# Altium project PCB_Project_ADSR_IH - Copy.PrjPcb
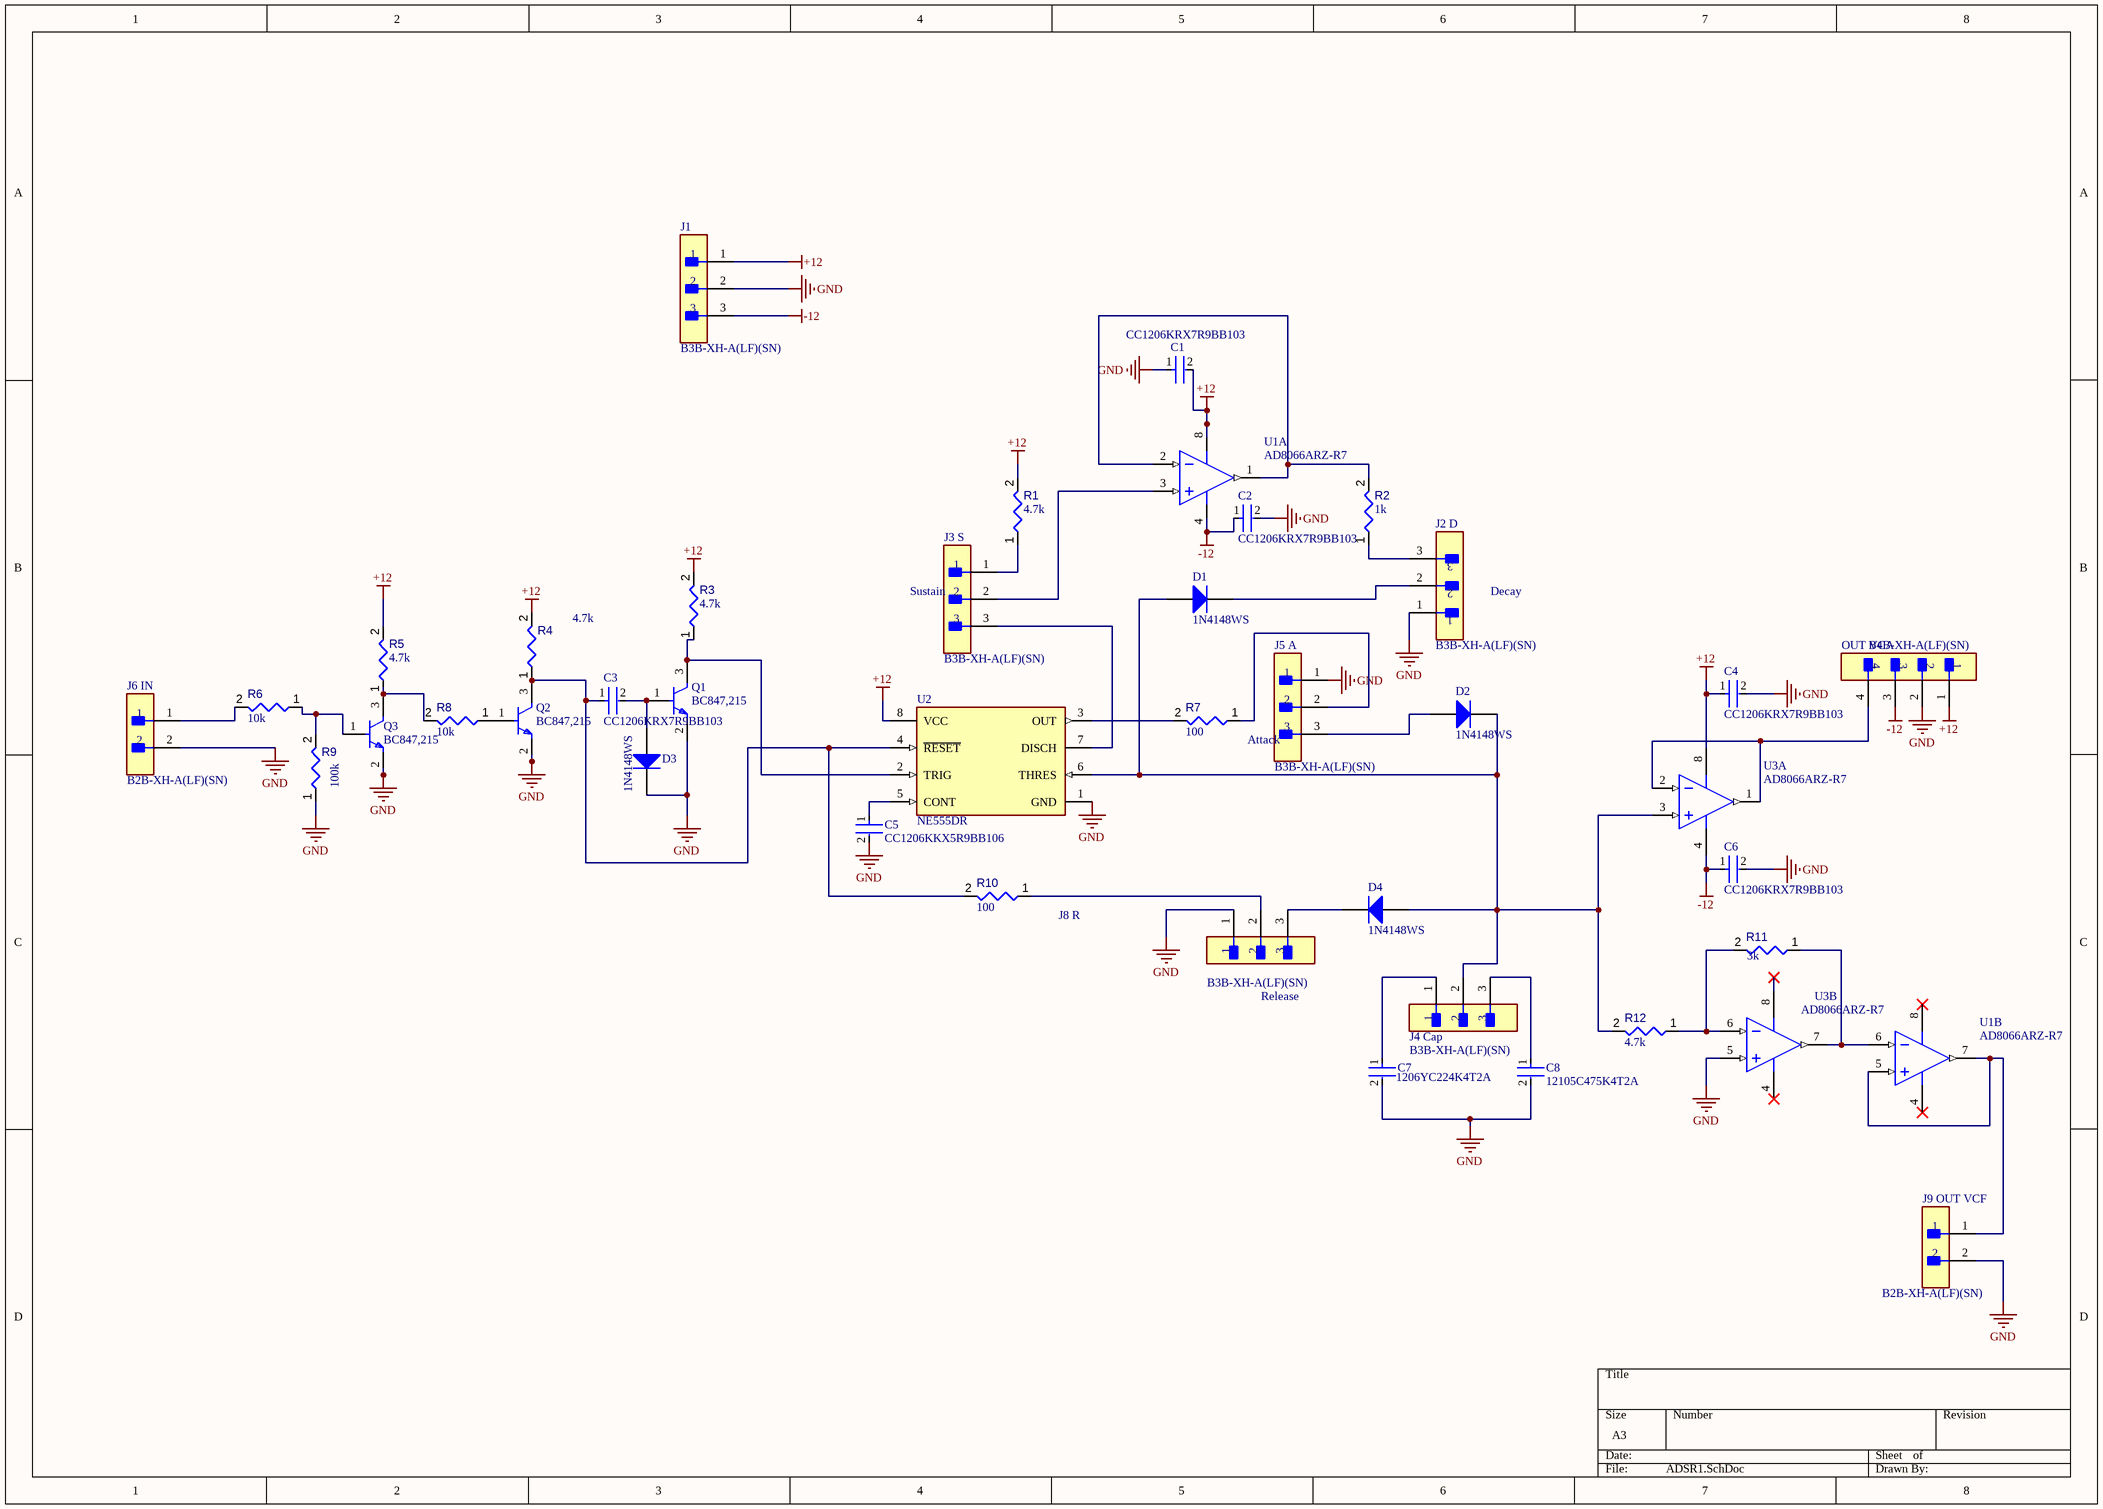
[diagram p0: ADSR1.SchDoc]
1 sheet, 39 parts. Net scope: global (net labels, ports and power ports of the same name join across sheets).
Board file: ADSR_pcb1.1.PcbDoc

## Sheet ADSR1.SchDoc: ADSR schematic
size A3; CheckedBy: Ingmar Kosmijer; Author: Hidde Huysman; CompanyName: Proj Synth; DrawnBy: Ingmar Kosmijer & Hidde Huysman; Organization: Windesheim College; Revision: 1.0; SheetNumber: 1; SheetTotal: 1

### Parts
C1  CC1206KRX7R9BB103  [FP-CC1206-1_25-MFG]
C2  CC1206KRX7R9BB103  [FP-CC1206-1_25-MFG]
C3  CC1206KRX7R9BB103  [FP-CC1206-1_25-MFG]
C4  CC1206KRX7R9BB103  [FP-CC1206-1_25-MFG]
C5  CC1206KKX5R9BB106  [FP-CC1206-FD-MFG]
C6  CC1206KRX7R9BB103  [FP-CC1206-1_25-MFG]
C7  1206YC224K4T2A  [FP-1206-L_3_2_0_2-W_1_6_0-IPC_B]
C8  12105C475K4T2A  [FP-1210-L_3_3_0_4-W_2_5_0-MFG]
D1  1N4148WS  [DIOD-SOD323-2-A_V]
D2  1N4148WS  [DIOD-SOD323-2-A_V]
D3  1N4148WS  [DIOD-SOD323-2-A_V]
D4  1N4148WS  [DIOD-SOD323-2-A_V]
J1  B3B-XH-A(LF)(SN)  [FP-B3B-XH-A_LF_SN-MFG]
J2_D  B3B-XH-A(LF)(SN)  [FP-B3B-XH-A_LF_SN-MFG]
J3_S  B3B-XH-A(LF)(SN)  [FP-B3B-XH-A_LF_SN-MFG]
J4_Cap  B3B-XH-A(LF)(SN)  [FP-B3B-XH-A_LF_SN-MFG]
J5_A  B3B-XH-A(LF)(SN)  [FP-B3B-XH-A_LF_SN-MFG]
J6_IN  B2B-XH-A(LF)(SN)  [FP-B2B-XH-A_LF_SN-MFG]
J8_R  B3B-XH-A(LF)(SN)  [FP-B3B-XH-A_LF_SN-MFG]
J9_OUT_VCF  B2B-XH-A(LF)(SN)  [FP-B2B-XH-A_LF_SN-MFG]
OUT_VCA  B4B-XH-A(LF)(SN)  [FP-B4B-XH-A_LF_SN-MFG]
Q1  BC847,215  [FP-SOT23-MFG]
Q2  BC847,215  [FP-SOT23-MFG]
Q3  BC847,215  [FP-SOT23-MFG]
R1  value 4.7k  [RESC3216X60X45ML15T20]  (hidden comment: Resistor 100k +/-1% 1206 250 mW)
R2  value 1k  [RESC2010(5025)_L]  (hidden comment: CRCW2010100RFKEF)
R3  value 4.7k  [RESC3216X60X45ML15T20]  (hidden comment: Resistor 100k +/-1% 1206 250 mW)
R4  value 4.7k  [RESC3216X60X45ML15T20]  (hidden comment: Resistor 100k +/-1% 1206 250 mW)
R5  value 4.7k  [RESC3216X60X45ML15T20]  (hidden comment: Resistor 100k +/-1% 1206 250 mW)
R6  value 10k  [RESC3216X60X45ML15T20]  (hidden comment: Resistor 100k +/-1% 1206 250 mW)
R7  value 100  [RESC3216X60X45ML15T20]  (hidden comment: Resistor 100k +/-1% 1206 250 mW)
R8  value 10k  [RESC3216X60X45ML15T20]  (hidden comment: Resistor 100k +/-1% 1206 250 mW)
R9  value 100k  [RESC3216X60X45ML15T20]  (hidden comment: Resistor 100k +/-1% 1206 250 mW)
R10  value 100  [RESC3216X60X45ML15T20]  (hidden comment: Resistor 100k +/-1% 1206 250 mW)
R11  value 3k  [RESC3216X60X45ML15T20]  (hidden comment: Resistor 100k +/-1% 1206 250 mW)
R12  value 4.7k  [RESC3216X60X45ML15T20]  (hidden comment: Resistor 100k +/-1% 1206 250 mW)
U1  AD8066ARZ-R7  [ADI-R-8_M]  (parts A,B of 2)
U2  NE555DR  [FP-D0008A-IPC_A]
U3  AD8066ARZ-R7  [ADI-R-8_M]  (parts A,B of 2)

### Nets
+12: C1.2 C4.1 J1.1 OUT_VCA.1 R1.2 R3.2 R4.2 R5.2 U1.8(+VS) U2.8(VCC) U3.8(+VS)
-12: C2.1 C6.1 J1.3 OUT_VCA.3 U1.4(-VS) U3.4(-VS)
GND: C1.1 C2.2 C4.2 C5.2 C6.2 C7.2 C8.2 D3.2(K) J1.2 J2_D.1 J5_A.1 J6_IN.2 J8_R.1 J9_OUT_VCF.2 OUT_VCA.2 Q1.2(E) Q2.2(E) Q3.2(E) R9.1 U2.1(GND) U3.5(+IN_2)
NetC3_1: C3.1 Q2.3(C) R4.1 R10.2 U2.4(~{RESET})
NetC3_2: C3.2 D3.1(A) Q1.1(B)
NetC5_1: C5.1 U2.5(CONT)
NetC7_1: C7.1 J4_Cap.1
NetC8_1: C8.1 J4_Cap.3
NetD1_1: D1.1(A) D2.2(K) D4.1(A) J4_Cap.2 R12.2 U2.6(THRES) U3.3(+IN_1)
NetD1_2: D1.2(K) J2_D.2
NetD2_1: D2.1(A) J5_A.3
NetD4_2: D4.2(K) J8_R.3
NetJ2_D_3: J2_D.3 R2.1
NetJ3_S_1: J3_S.1 R1.1
NetJ3_S_2: J3_S.2 U1.3(+IN_1)
NetJ3_S_3: J3_S.3 U2.7(DISCH)
NetJ5_A_2: J5_A.2 R7.1
NetJ6_IN_1: J6_IN.1 R6.2
NetJ8_R_2: J8_R.2 R10.1
NetJ9_OUT_VCF_1: J9_OUT_VCF.1 U1.5(+IN_2) U1.7(VOUT_2)
NetOUT_VCA_4: OUT_VCA.4 U3.1(VOUT_1) U3.2(-IN_1)
NetQ1_3: Q1.3(C) R3.1 U2.2(TRIG)
NetQ2_1: Q2.1(B) R8.1
NetQ3_1: Q3.1(B) R6.1 R9.2
NetQ3_3: Q3.3(C) R5.1 R8.2
NetR2_2: R2.2 U1.1(VOUT_1) U1.2(-IN_1)
NetR7_2: R7.2 U2.3(OUT)
NetR11_1: R11.1 U1.6(-IN_2) U3.7(VOUT_2)
NetR11_2: R11.2 R12.1 U3.6(-IN_2)

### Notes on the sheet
- (near J3_S) Sustain
- Decay
- Attack
- Release

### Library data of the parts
C1-C4 C6 = CMP-1037-03511-2: CAP CER 10000PF 50V X7R 1206; Manufacturer: Yageo; Automotive Grade: NA; Temperature Coefficient: 15%; Tolerance: 0.1; Capacitance: 10 nF; Value: 10 nF; Material: Ceramic
C5 = CMP-03422-001420-1: CAP CER 10UF 50V X5R 1206; Tolerance: 10%
C7 = CMP-04427-019066-1: Automotive Ceramic Capacitor, 1206, 220nF, 10%, X7R, 15%, 16V
C8 = CMP-04427-006002-1: Automotive Ceramic Capacitor, 1210, 4.7uF, 10%, X7R, 15%, 50V
D1-D4 = CMP-004-00002-2: Fast Switching Diode, 75 V, 0.3 A, -65 to 150 degC, 2-Pin SOD323, RoHS, Tape and Reel; Manufacturer: Diodes Inc; Peak Reverse Current: 1uA; Max Surge Current: 2A; Elements: 1; Forward Current: 300mA; Recovery Time: 4ns; Forward Voltage: 1.25V
J1 J2_D J3_S J4_Cap J5_A J8_R = CMP-17439-000014-3: CONN HEADER VERT 3POS 2.5MM; Max Voltage Rating (DC): 250V; Number of Positions: 3; Current Rating: 3A; Gender: Male; Wire/Cable Gauge: 22AWG; Contact Resistance: 20mR; Insulation Resistance: 1GR
J6_IN J9_OUT_VCF = CMP-2000-05888-3: CONN HEADER VERT 2POS 2.5MM; Current Rating: 3A; Voltage Rating: 250V; Number of Contacts: 2; Contact Resistance: 20mR; Wire/Cable Gauge: 22AWG; Insulation Resistance: 1GR; Connector Type: Male Pin
OUT_VCA = CMP-17439-000250-1: CONN HEADER VERT 4POS 2.5MM; Number of Contacts: 4; Contact Resistance: 20mR; Voltage Rating: 250V; Max Current Rating: 3A; Gender: Male; Wire/Cable Gauge: 22AWG; Mated Stacking Heights: 9.8mm; Insulation Resistance: 1GR
Q1-Q3 = CMP-14406-000009-1: TRANS NPN 45V 0.1A SOT23; Manufacturer: Nexperia; Max Collector Current: 100mA; Hfe Testvce: 5V; Hfe Testic: 2mA; Number Of Npn: 1; Max Junction Temp: +150°C; Collector Base Voltage: 50V; Hfe Max: 800; Power Dissipation: 250mW; Emitter Base Voltage: 6V; Automotive Grade: Grade 0; Gain Bandwidth Product: 100MHz; Rthja Max: 500K/W; Collector Emitter Saturation Voltage: 200mV; Hfe Min: 110
R1 R3-R12 = CMP-009-00025-5: Chip Resistor, 100 KOhm, +/- 1%, 0.25 W, -55 to 155 degC, 1206 (3216 Metric); Voltage Rating: 200V; Power: 250mW
R2 = CMP-009-00178-1: Fixed Resistor, Metal Glaze/thick Film, 0.75W, 100ohm, 400V, 1% +/-Tol, 100ppm/Cel, Surface Mount, 2010; Power: 750mW
U1 U3 = CMP-0384-01346-2: Double Channel Low Power Operational Amplifier, 145 MHz BW, 180 V/us SR, Industrial, 8-pin SOIC (R-8), Reel; Manufacturer: Analog Devices; Generic Part Number: AD8066; Small Signal Bandwidth: 145MHz; V Span Min: 5V; Input Offset Voltage: 400uV; V Span Max: 24V; Input Bias Current: 2pA; Amplifiers Per Package: 2; Iq/Amp: 7.4mA
U2 = CMP-1685-00007-2: IC OSC SGL TIMER 100KHZ 8-SOIC; Low Level Output Current: 200mA; Quiescent Current: 15mA; Min Supply Voltage: 4.5V; Number of Timers/Counters: 1; Max Supply Voltage: 16V; Operating Supply Current: 10mA; High Level Output Current: -200mA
